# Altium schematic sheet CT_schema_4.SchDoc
size 282 x 169 mm
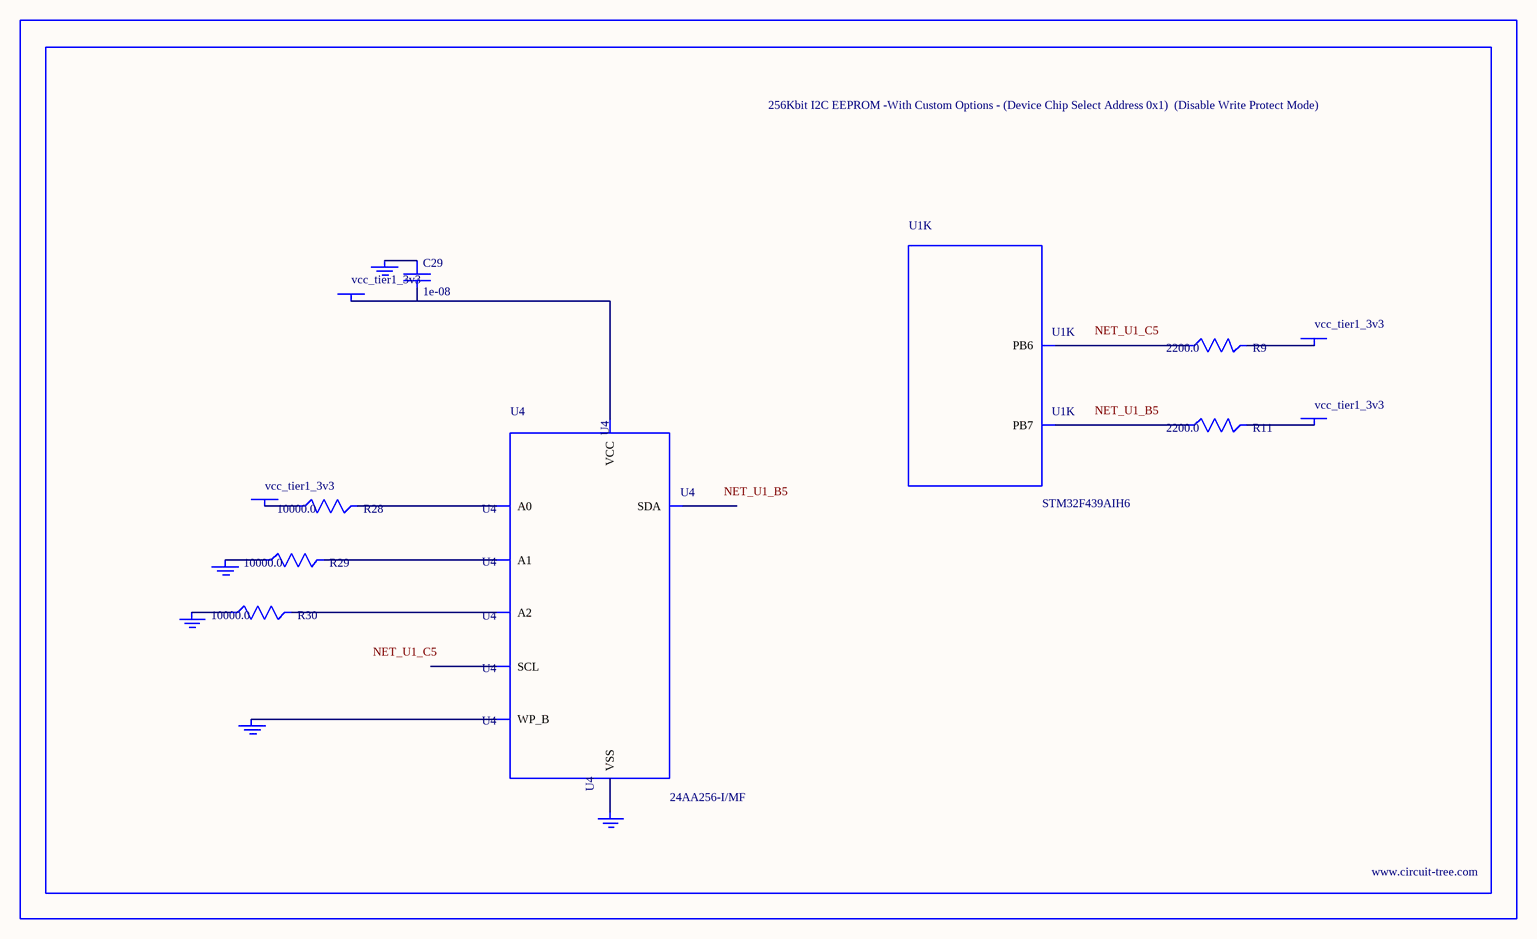
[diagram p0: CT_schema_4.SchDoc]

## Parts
BORDER3  (no value)
C29  1e-08  [C0402]
GND_INSTANCE_3_0  (no value)
GND_INSTANCE_3_1  (no value)
GND_INSTANCE_3_2  (no value)
GND_INSTANCE_3_3  (no value)
GND_INSTANCE_3_4  (no value)
POWER_INSTANCE_3_0  vcc_tier1_3v3
POWER_INSTANCE_3_1  vcc_tier1_3v3
POWER_INSTANCE_3_2  vcc_tier1_3v3
POWER_INSTANCE_3_3  vcc_tier1_3v3
R9  2200.0  [R0603]
R11  2200.0  [R0603]
R28  10000.0  [R0603]
R29  10000.0  [R0603]
R30  10000.0  [R0603]
U1  STM32F439AIH6  [UFBGA169]  (part K of 12)
U4  24AA256-I/MF  [DFN8-S]

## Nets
NetC29_1: C29.1 GND_INSTANCE_3_3.0(GND)
NetC29_2: C29.2 POWER_INSTANCE_3_1.0(PWR) U4.8(VCC)
NetGND_INSTANCE_3_0_0: GND_INSTANCE_3_0.0(GND) R29.1
NetGND_INSTANCE_3_1_0: GND_INSTANCE_3_1.0(GND) R30.1
NetGND_INSTANCE_3_2_0: GND_INSTANCE_3_2.0(GND) U4.7(WP_B)
NetGND_INSTANCE_3_4_0: GND_INSTANCE_3_4.0(GND) U4.4(VSS)
NetPOWER_INSTANCE_3_0_0: POWER_INSTANCE_3_0.0(PWR) R28.1
NetPOWER_INSTANCE_3_2_0: POWER_INSTANCE_3_2.0(PWR) R9.2
NetPOWER_INSTANCE_3_3_0: POWER_INSTANCE_3_3.0(PWR) R11.2
NetR9_1: R9.1 U1.C5(PB6)
NetR11_1: R11.1 U1.B5(PB7)
NetR28_2: R28.2 U4.1(A0)
NetR29_2: R29.2 U4.2(A1)
NetR30_2: R30.2 U4.3(A2)

Not connected (* = marked no-connect by the designer): U4 5(SDA) 6(SCL)

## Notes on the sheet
- Labels drawn without touching a wire or pin: NET_U1_B5, NET_U1_C5

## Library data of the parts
BORDER3 = BORDER_PAGE3
C29 = C0402C103K3RAC
GND_INSTANCE_3_0-GND_INSTANCE_3_4 = GND
POWER_INSTANCE_3_0-POWER_INSTANCE_3_3 = PWR
R9 R11 = RC0603JR-072K2L
R28-R30 = RC0603JR-0710KL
